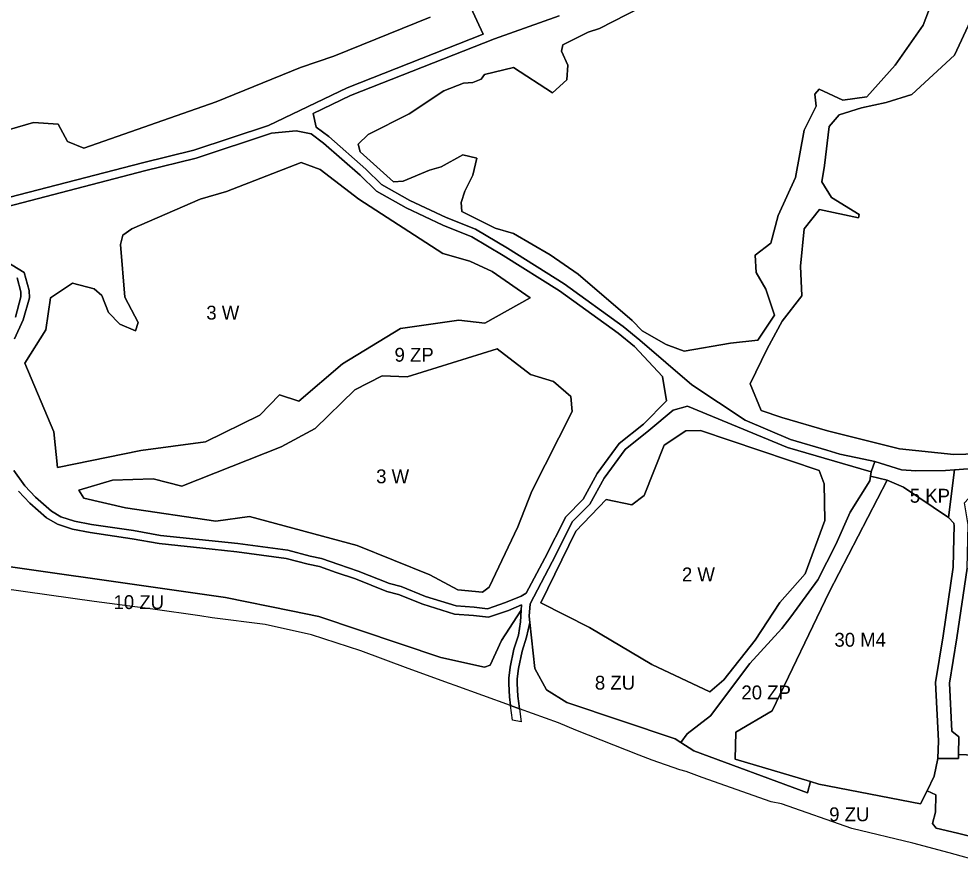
# Model space of a CAD drawing. Extents: x 7437831 to 7440315, y 5545798 to 5547888.
# Drawn here: x 7438706 to 7439385, y 5545907 to 5546523 of the extents above; entities that cross this region are included whole.
import ezdxf

# ---------------------------------------------------------------- set-up
doc = ezdxf.new("R2010")
doc.units = 0
doc.layers.add('linie_rozgraniczajace', color=7, linetype='Continuous')
doc.layers.add('oznaczenia_przeznaczen', color=7, linetype='Continuous')

msp = doc.modelspace()

# ---------------------------------------------------------------- linework, layer by layer
at = {"layer": 'linie_rozgraniczajace'}
for points in [[(7438699.06, 5546673.83), (7438708.8, 5546695.84), (7438713.9, 5546712.14), (7438733.41, 5546751.01), (7438750.34, 5546785.38), (7438759.15, 5546802.74), (7438764.03, 5546813.26), (7438765.56, 5546815.87), (7438771.94, 5546819.42), (7438985.17, 5546680.77), (7439014.11, 5546648.75), (7439017.47, 5546636.36), (7439017.35, 5546621.89), (7439016.94, 5546607.19), (7439014.18, 5546578.97), (7439018.45, 5546567.43), (7439030.64, 5546534.44), (7439041.15, 5546511.43), (7438943, 5546472.84), (7438886.32, 5546445.62), (7438832.51, 5546427.97), (7438795.44, 5546418.73), (7438685.57, 5546390.27)], [(7438685.57, 5546390.27), (7438795.44, 5546418.73), (7438832.51, 5546427.97), (7438886.32, 5546445.62), (7438943, 5546472.84), (7439041.15, 5546511.43), (7439030.64, 5546534.44), (7439018.45, 5546567.43), (7439014.18, 5546578.97), (7439016.94, 5546607.19), (7439017.35, 5546621.89), (7439017.47, 5546636.36), (7439014.11, 5546648.75), (7438985.17, 5546680.77), (7438771.94, 5546819.42), (7438765.56, 5546815.87), (7438764.03, 5546813.26), (7438759.15, 5546802.74), (7438750.34, 5546785.38), (7438733.41, 5546751.01), (7438713.9, 5546712.14), (7438708.8, 5546695.84), (7438699.06, 5546673.83)], [(7439401.45, 5546576.44), (7439379.25, 5546577.57), (7439374.12, 5546559.74), (7439358.43, 5546518.01), (7439338.09, 5546489.26), (7439317.74, 5546466.42), (7439300.33, 5546464.03), (7439283.42, 5546471.79), (7439280.22, 5546468.33), (7439281.31, 5546459.59), (7439272.68, 5546442.36), (7439266.36, 5546408.09), (7439253.82, 5546380.88), (7439248.46, 5546360.85)], [(7439164.87, 5546535.91), (7439125.09, 5546515.56), (7439116.92, 5546513.02), (7439098.56, 5546503.88), (7439097.54, 5546499.33), (7439102.06, 5546489.25), (7439101.55, 5546478.52), (7439091.04, 5546469.2), (7439063.01, 5546487.51), (7439042.01, 5546482.37), (7439039.75, 5546479.03), (7439033.58, 5546476.61), (7439026.99, 5546476.08), (7439012.79, 5546470.71), (7438987.75, 5546454.06), (7438958.16, 5546439.08), (7438950.98, 5546432.24), (7438952.33, 5546426.57), (7438976.57, 5546405.02), (7438983.43, 5546405.41), (7439002.39, 5546413.45), (7439010.83, 5546415.84), (7439026.4, 5546424.54), (7439036.63, 5546422.09), (7439033.54, 5546409.92), (7439027.88, 5546398.25), (7439025.26, 5546390.04), (7439025.83, 5546383.57), (7439049.69, 5546371.71), (7439063.06, 5546367.71), (7439089.41, 5546352.3), (7439109.68, 5546338.47), (7439148.63, 5546305.03), (7439155.7, 5546297.64), (7439173.07, 5546287.72), (7439174.97, 5546286.99), (7439185.95, 5546282.96), (7439219.38, 5546288.65), (7439239.17, 5546290.83), (7439251.23, 5546308.83), (7439244.94, 5546327.59), (7439237.88, 5546339.63), (7439237.29, 5546352.21), (7439248.46, 5546360.85), (7439253.82, 5546380.88), (7439266.36, 5546408.09), (7439272.68, 5546442.36), (7439281.31, 5546459.59), (7439280.22, 5546468.33), (7439283.42, 5546471.79), (7439300.33, 5546464.03), (7439317.74, 5546466.42), (7439338.09, 5546489.26), (7439358.43, 5546518.01), (7439374.12, 5546559.74)], [(7439248.46, 5546360.85), (7439237.29, 5546352.21), (7439237.88, 5546339.63), (7439244.94, 5546327.59), (7439251.23, 5546308.83), (7439239.17, 5546290.83), (7439219.38, 5546288.65), (7439185.95, 5546282.96), (7439174.97, 5546286.99), (7439173.07, 5546287.72), (7439155.7, 5546297.64), (7439148.63, 5546305.03), (7439109.68, 5546338.47), (7439089.41, 5546352.3), (7439063.06, 5546367.71), (7439049.69, 5546371.71), (7439025.83, 5546383.57), (7439025.26, 5546390.04), (7439027.88, 5546398.25), (7439033.54, 5546409.92), (7439036.63, 5546422.09), (7439026.4, 5546424.54), (7439010.83, 5546415.84), (7439002.39, 5546413.45), (7438983.43, 5546405.41), (7438976.57, 5546405.02), (7438952.33, 5546426.57), (7438950.98, 5546432.24), (7438958.16, 5546439.08), (7438987.75, 5546454.06), (7439012.79, 5546470.71), (7439026.99, 5546476.08), (7439033.58, 5546476.61), (7439039.75, 5546479.03), (7439042.01, 5546482.37), (7439063.01, 5546487.51), (7439091.04, 5546469.2), (7439101.55, 5546478.52), (7439102.06, 5546489.25), (7439097.54, 5546499.33), (7439098.56, 5546503.88), (7439116.92, 5546513.02), (7439125.09, 5546515.56), (7439164.87, 5546535.91)], [(7438699.67, 5546442.72), (7438716.97, 5546447.82), (7438734.58, 5546446.64), (7438741.43, 5546434.19), (7438753.16, 5546429.4), (7438848.5, 5546462.71), (7438909.43, 5546487.42), (7438933.42, 5546495.59), (7439002.86, 5546523.66)], [(7439002.86, 5546523.66), (7438933.42, 5546495.59), (7438909.43, 5546487.42), (7438848.5, 5546462.71), (7438753.16, 5546429.4), (7438741.43, 5546434.19), (7438734.58, 5546446.64), (7438716.97, 5546447.82), (7438699.67, 5546442.72)], [(7439095.95, 5546524.77), (7439049.23, 5546508.17), (7438945.4, 5546467.33), (7438918.44, 5546454.39), (7438920.74, 5546444.4), (7438929.86, 5546437.61), (7438956.57, 5546414.17), (7438967.72, 5546403.03), (7438988.32, 5546391.65), (7439014.38, 5546379.2), (7439035.51, 5546370.91), (7439058.75, 5546357.15), (7439099.4, 5546331.47), (7439142.06, 5546300.79), (7439154.08, 5546290.95), (7439191.67, 5546258.77), (7439230.13, 5546233.17), (7439262.63, 5546219.23), (7439288.89, 5546211.59), (7439298.31, 5546208.73), (7439315.6, 5546205.08), (7439323.52, 5546203.36), (7439320.99, 5546196.02), (7439260.6, 5546213.58), (7439188.38, 5546243.2), (7439178.2, 5546240.33), (7439160.56, 5546225.69), (7439143.61, 5546212.17), (7439128.44, 5546191.44), (7439117.98, 5546172.55), (7439105.53, 5546160.06), (7439090.84, 5546130.96), (7439074.92, 5546100.81), (7439074.32, 5546091.83), (7439074.82, 5546087.34), (7439072.38, 5546076.79), (7439069.13, 5546066.7), (7439066.53, 5546054.14), (7439065.7, 5546046.83), (7439065.65, 5546043.25), (7439066.09, 5546034.32), (7439066.92, 5546029.01), (7439067.36, 5546025.17), (7439060.74, 5546027.56), (7439060.11, 5546033.71), (7439059.65, 5546043.15), (7439059.71, 5546047.21), (7439060.6, 5546055.09), (7439063.32, 5546068.23), (7439066.53, 5546078.18), (7439068.05, 5546087.92), (7439068.61, 5546096.26), (7439068.85, 5546100), (7439059.4, 5546096.08), (7439044.88, 5546091.15), (7439034.11, 5546092.42), (7439020.47, 5546093.46), (7438997.61, 5546100.51), (7438979.99, 5546107.49), (7438971.76, 5546109.7), (7438949.01, 5546118.76), (7438935.17, 5546123.37), (7438922.98, 5546127.76), (7438914.96, 5546129.33), (7438899.12, 5546133.51), (7438863.46, 5546138.4), (7438845.67, 5546140.31), (7438807.57, 5546144.23), (7438788, 5546147.71), (7438757.75, 5546152.15), (7438744.93, 5546154.58), (7438734.21, 5546158.12), (7438726.22, 5546162.82), (7438714.2, 5546173.33), (7438706.01, 5546182.06)], [(7439400.62, 5546198.75), (7439380.94, 5546197.47), (7439374.36, 5546197.04), (7439353.15, 5546196.65), (7439342.8, 5546197.49), (7439323.52, 5546203.36), (7439315.6, 5546205.08), (7439298.31, 5546208.73), (7439288.89, 5546211.59), (7439262.63, 5546219.23), (7439230.13, 5546233.17), (7439191.67, 5546258.77), (7439154.08, 5546290.95), (7439142.06, 5546300.79), (7439099.4, 5546331.47), (7439058.75, 5546357.15), (7439035.51, 5546370.91), (7439014.38, 5546379.2), (7438988.32, 5546391.65), (7438967.72, 5546403.03), (7438956.57, 5546414.17), (7438929.86, 5546437.61), (7438920.74, 5546444.4), (7438918.44, 5546454.39), (7438945.4, 5546467.33), (7439049.23, 5546508.17), (7439095.95, 5546524.77)], [(7439423.56, 5546209.6), (7439380.47, 5546208.46), (7439341.2, 5546212.43), (7439289.29, 5546225.51), (7439256.48, 5546235.14), (7439241.51, 5546240.13), (7439233.66, 5546259.37), (7439245.78, 5546284.53), (7439256.59, 5546304.63), (7439270.79, 5546322.75), (7439269.92, 5546344.23), (7439272.48, 5546371.23), (7439283.6, 5546384.98), (7439311.64, 5546379.12), (7439312.27, 5546381.43), (7439292.35, 5546393.79), (7439285.23, 5546404.92), (7439287.18, 5546416.79), (7439290.51, 5546444.98), (7439297.72, 5546453.43), (7439313.99, 5546458.47), (7439331.7, 5546462.18), (7439350.24, 5546467.97), (7439380.9, 5546496.43), (7439392.56, 5546521.09)], [(7439392.56, 5546521.09), (7439380.9, 5546496.43), (7439350.24, 5546467.97), (7439331.7, 5546462.18), (7439313.99, 5546458.47), (7439297.72, 5546453.43), (7439290.51, 5546444.98)], [(7438687, 5546384.45), (7438796.92, 5546412.91), (7438834.17, 5546422.2), (7438888.57, 5546440.05), (7438906.24, 5546441.88), (7438917.16, 5546439.59), (7438926.08, 5546432.94), (7438952.47, 5546409.79), (7438964.08, 5546398.19), (7438985.58, 5546386.31), (7439011.99, 5546373.7), (7439032.87, 5546365.5), (7439055.62, 5546352.03), (7439096.04, 5546326.5), (7439138.41, 5546296.03), (7439150.19, 5546286.39), (7439170.34, 5546264.59), (7439173.21, 5546247.17), (7439156.78, 5546230.34), (7439139.25, 5546216.36), (7439123.38, 5546194.68), (7439113.14, 5546176.19), (7439100.61, 5546163.61), (7439085.51, 5546133.71), (7439072.14, 5546108.39), (7439068.56, 5546106.37), (7439057.28, 5546101.7), (7439044.23, 5546097.27), (7439034.68, 5546098.4), (7439021.59, 5546099.39), (7438999.6, 5546106.18), (7438981.88, 5546113.2), (7438973.66, 5546115.41), (7438951.07, 5546124.39), (7438937.13, 5546129.04), (7438924.58, 5546133.56), (7438916.3, 5546135.18), (7438900.29, 5546139.4), (7438864.19, 5546144.36), (7438808.41, 5546150.18), (7438788.96, 5546153.63), (7438758.74, 5546158.07), (7438746.44, 5546160.4), (7438736.7, 5546163.61), (7438729.75, 5546167.71), (7438718.37, 5546177.65), (7438710.65, 5546185.88), (7438702.73, 5546196.88)], [(7438702.73, 5546196.88), (7438710.65, 5546185.88), (7438718.37, 5546177.65), (7438729.75, 5546167.71), (7438736.7, 5546163.61), (7438746.44, 5546160.4), (7438758.74, 5546158.07), (7438788.96, 5546153.63), (7438808.41, 5546150.18), (7438864.19, 5546144.36), (7438900.29, 5546139.4), (7438916.3, 5546135.18), (7438924.58, 5546133.56), (7438937.13, 5546129.04), (7438951.07, 5546124.39), (7438973.66, 5546115.41), (7438981.88, 5546113.2), (7438999.6, 5546106.18), (7439021.59, 5546099.39), (7439034.68, 5546098.4), (7439044.23, 5546097.27), (7439057.28, 5546101.7), (7439068.56, 5546106.37), (7439072.14, 5546108.39), (7439085.51, 5546133.71), (7439100.61, 5546163.61), (7439113.14, 5546176.19), (7439123.38, 5546194.68), (7439139.25, 5546216.36), (7439156.78, 5546230.34), (7439173.21, 5546247.17), (7439170.34, 5546264.59), (7439150.19, 5546286.39), (7439138.41, 5546296.03), (7439096.04, 5546326.5), (7439055.62, 5546352.03), (7439032.87, 5546365.5), (7439011.99, 5546373.7), (7438985.58, 5546386.31), (7438964.08, 5546398.19), (7438952.47, 5546409.79), (7438926.08, 5546432.94), (7438917.16, 5546439.59), (7438906.24, 5546441.88), (7438888.57, 5546440.05), (7438834.17, 5546422.2), (7438796.92, 5546412.91), (7438687, 5546384.45)], [(7439290.51, 5546444.98), (7439287.18, 5546416.79), (7439285.23, 5546404.92), (7439292.35, 5546393.79), (7439312.27, 5546381.43), (7439311.64, 5546379.12), (7439283.6, 5546384.98), (7439272.48, 5546371.23), (7439269.92, 5546344.23), (7439270.79, 5546322.75), (7439256.59, 5546304.63), (7439245.78, 5546284.53), (7439233.66, 5546259.37), (7439241.51, 5546240.13), (7439256.48, 5546235.14), (7439289.29, 5546225.51), (7439341.2, 5546212.43), (7439380.47, 5546208.46), (7439423.56, 5546209.6)], [(7438703.19, 5546291.86), (7438709.44, 5546305.5), (7438713.88, 5546321.32), (7438713.77, 5546326.6), (7438710.19, 5546339.75), (7438692.64, 5546350.33)], [(7438692.64, 5546350.33), (7438710.19, 5546339.75), (7438713.77, 5546326.6), (7438713.88, 5546321.32), (7438709.44, 5546305.5), (7438703.19, 5546291.86)], [(7438705.04, 5546335.85), (7438707.78, 5546325.74), (7438707.86, 5546322.08), (7438703.79, 5546307.58)], [(7438703.79, 5546307.58), (7438707.86, 5546322.08), (7438707.78, 5546325.74), (7438705.04, 5546335.85)], [(7439389.99, 5546126.42), (7439382.67, 5546076.21), (7439377.24, 5546043.59), (7439379.16, 5546008.91), (7439384.02, 5546004.85), (7439383.92, 5545992.14), (7439383.9, 5545989.36), (7439369.04, 5545989.31), (7439369.31, 5546001.99), (7439367.2, 5546044.17), (7439372.79, 5546077.75), (7439380.01, 5546127.27), (7439380.55, 5546148.21), (7439380.78, 5546157.06), (7439380.49, 5546158.88), (7439376.7, 5546163.04), (7439380.94, 5546197.47), (7439400.62, 5546198.75)], [(7438706.01, 5546182.06), (7438714.2, 5546173.33), (7438726.22, 5546162.82), (7438734.21, 5546158.12), (7438744.93, 5546154.58), (7438757.75, 5546152.15), (7438788, 5546147.71), (7438807.57, 5546144.23), (7438845.67, 5546140.31), (7438863.46, 5546138.4), (7438899.12, 5546133.51), (7438914.96, 5546129.33), (7438922.98, 5546127.76), (7438935.17, 5546123.37), (7438949.01, 5546118.76), (7438971.76, 5546109.7), (7438979.99, 5546107.49), (7438997.61, 5546100.51), (7439020.47, 5546093.46), (7439034.11, 5546092.42), (7439044.88, 5546091.15), (7439059.4, 5546096.08), (7439068.85, 5546100), (7439068.61, 5546096.26), (7439054.32, 5546074.41), (7439046.11, 5546056.67), (7439042.09, 5546055.06), (7439010.65, 5546062.01), (7438922.67, 5546091.62), (7438902.67, 5546095.84), (7438855.21, 5546105.38), (7438641.23, 5546135.98)], [(7438641.23, 5546135.98), (7438855.21, 5546105.38), (7438902.67, 5546095.84), (7438922.67, 5546091.62), (7439010.65, 5546062.01), (7439042.09, 5546055.06), (7439046.11, 5546056.67), (7439054.32, 5546074.41), (7439068.61, 5546096.26), (7439068.05, 5546087.92), (7439066.53, 5546078.18), (7439063.32, 5546068.23), (7439060.6, 5546055.09), (7439059.71, 5546047.21), (7439059.65, 5546043.15), (7439060.11, 5546033.71), (7439060.74, 5546027.56), (7439020.85, 5546041.97), (7439016.86, 5546043.42), (7438987.05, 5546054.19), (7438952.89, 5546066.82), (7438917.26, 5546078.42), (7438883.95, 5546085.91), (7438845.69, 5546090.69), (7438836.78, 5546092.12), (7438803.01, 5546097.03), (7438760.54, 5546102.46), (7438693.97, 5546111.88)], [(7439401.35, 5545914.55), (7439377.07, 5545921.34), (7439350.86, 5545928.25), (7439306.97, 5545938.71), (7439256.27, 5545956.7), (7439248.87, 5545958.09), (7439199.01, 5545975.54), (7439187.44, 5545979.82), (7439182.82, 5545981.12), (7439162.87, 5545988.13), (7439153.49, 5545991.61), (7439107.99, 5546009.8), (7439095.39, 5546015.05), (7439067.36, 5546025.17), (7439066.92, 5546029.01), (7439066.09, 5546034.32), (7439065.65, 5546043.25), (7439065.7, 5546046.83), (7439066.53, 5546054.14), (7439069.13, 5546066.7), (7439072.38, 5546076.79), (7439074.82, 5546087.34), (7439078.44, 5546054.28), (7439086.74, 5546038.75), (7439101.49, 5546029.72), (7439179.66, 5546003.41), (7439183.66, 5546000.85), (7439192.93, 5545994.92), (7439275.05, 5545964.63), (7439277.14, 5545972.67), (7439283.09, 5545970.89), (7439356.55, 5545956.51), (7439361.22, 5545966.06), (7439367.55, 5545963.07), (7439367.18, 5545950.71), (7439365.08, 5545942.43), (7439367.76, 5545939.03), (7439383.16, 5545935.37), (7439495.91, 5545907.34)], [(7439495.91, 5545907.34), (7439383.16, 5545935.37), (7439367.76, 5545939.03), (7439365.08, 5545942.43), (7439367.18, 5545950.71), (7439367.55, 5545963.07), (7439361.22, 5545966.06), (7439366.36, 5545976.59), (7439369.04, 5545989.31), (7439383.9, 5545989.36), (7439383.92, 5545992.14), (7439406.69, 5545991.33)]]:
    msp.add_lwpolyline(points, dxfattribs=at)
for points in [[(7438840.99, 5546217.59), (7438880.15, 5546236.92), (7438894.18, 5546251.37), (7438908.31, 5546246.92), (7438939.58, 5546273.72), (7438981.4, 5546299.33), (7439023.6, 5546305.28), (7439042.27, 5546303.24), (7439074.95, 5546321.49), (7439047.53, 5546340.35), (7439031.52, 5546347.85), (7439011.94, 5546353.36), (7438951.56, 5546392.46), (7438923.48, 5546414.02), (7438909.93, 5546419.07), (7438856.12, 5546398.13), (7438837.11, 5546392.43), (7438787.89, 5546371.15), (7438781.39, 5546366.47), (7438779.67, 5546359.91), (7438782.8, 5546321.8), (7438792.37, 5546303.71), (7438790.48, 5546297.69), (7438779.03, 5546302.39), (7438771.01, 5546310.82), (7438766.11, 5546323.05), (7438760.65, 5546327.95), (7438744.96, 5546331.91), (7438729.15, 5546321.38), (7438725.86, 5546298.31), (7438710.59, 5546274.4), (7438731.66, 5546224.8), (7438734.12, 5546199.14), (7438794.31, 5546211.46)], [(7438840.99, 5546217.59), (7438794.31, 5546211.46), (7438734.12, 5546199.14), (7438731.66, 5546224.8), (7438710.59, 5546274.4), (7438725.86, 5546298.31), (7438729.15, 5546321.38), (7438744.96, 5546331.91), (7438760.65, 5546327.95), (7438766.11, 5546323.05), (7438771.01, 5546310.82), (7438779.03, 5546302.39), (7438790.48, 5546297.69), (7438792.37, 5546303.71), (7438782.8, 5546321.8), (7438779.67, 5546359.91), (7438781.39, 5546366.47), (7438787.89, 5546371.15), (7438837.11, 5546392.43), (7438856.12, 5546398.13), (7438909.93, 5546419.07), (7438923.48, 5546414.02), (7438951.56, 5546392.46), (7439011.94, 5546353.36), (7439031.52, 5546347.85), (7439047.53, 5546340.35), (7439074.95, 5546321.49), (7439042.27, 5546303.24), (7439023.6, 5546305.28), (7438981.4, 5546299.33), (7438939.58, 5546273.72), (7438908.31, 5546246.92), (7438894.18, 5546251.37), (7438880.15, 5546236.92)], [(7439045.51, 5546112.89), (7439066.08, 5546156.32), (7439076.27, 5546182.07), (7439105.21, 5546239.48), (7439104.37, 5546250.16), (7439091.9, 5546261.07), (7439075.16, 5546266.12), (7439051.11, 5546284.69), (7438986.29, 5546264.56), (7438968.28, 5546265.11), (7438948.53, 5546255), (7438919.87, 5546227.12), (7438895.48, 5546213.93), (7438823.82, 5546185.72), (7438803.21, 5546191.02), (7438773.75, 5546190.07), (7438749.55, 5546182.66), (7438753.24, 5546177.08), (7438783.26, 5546170.12), (7438848.36, 5546160.4), (7438872.71, 5546163.86), (7438950.29, 5546142.9), (7439002.73, 5546121.64), (7439022.89, 5546110.99), (7439040.71, 5546109.2)], [(7439045.51, 5546112.89), (7439040.71, 5546109.2), (7439022.89, 5546110.99), (7439002.73, 5546121.64), (7438950.29, 5546142.9), (7438872.71, 5546163.86), (7438848.36, 5546160.4), (7438783.26, 5546170.12), (7438753.24, 5546177.08), (7438749.55, 5546182.66), (7438773.75, 5546190.07), (7438803.21, 5546191.02), (7438823.82, 5546185.72), (7438895.48, 5546213.93), (7438919.87, 5546227.12), (7438948.53, 5546255), (7438968.28, 5546265.11), (7438986.29, 5546264.56), (7439051.11, 5546284.69), (7439075.16, 5546266.12), (7439091.9, 5546261.07), (7439104.37, 5546250.16), (7439105.21, 5546239.48), (7439076.27, 5546182.07), (7439066.08, 5546156.32)], [(7439188.38, 5546243.2), (7439260.6, 5546213.58), (7439320.99, 5546196.02), (7439320.51, 5546192.9), (7439319.98, 5546189.4), (7439305.67, 5546166.84), (7439295.37, 5546143.59), (7439282.36, 5546118.13), (7439263.03, 5546091.51), (7439256.36, 5546083.09), (7439233.48, 5546057.75), (7439204.95, 5546020.01), (7439188.18, 5546007.15), (7439183.66, 5546000.85), (7439179.66, 5546003.41), (7439101.49, 5546029.72), (7439086.74, 5546038.75), (7439078.44, 5546054.28), (7439074.82, 5546087.34), (7439074.32, 5546091.83), (7439074.92, 5546100.81), (7439090.84, 5546130.96), (7439105.53, 5546160.06), (7439117.98, 5546172.55), (7439128.44, 5546191.44), (7439143.61, 5546212.17), (7439160.56, 5546225.69), (7439178.2, 5546240.33)], [(7439171.56, 5546215.2), (7439157.3, 5546178.83), (7439148.3, 5546172.1), (7439129.75, 5546176.06), (7439108.04, 5546153.16), (7439082.77, 5546101.56), (7439117.88, 5546083.8), (7439162.82, 5546057.15), (7439204.63, 5546037.38), (7439214.55, 5546045.91), (7439237.21, 5546074.49), (7439255.12, 5546101.73), (7439273.31, 5546122.44), (7439287.56, 5546160.9), (7439287.03, 5546187.23), (7439283.33, 5546196.98), (7439197.74, 5546225.81), (7439187.13, 5546225.41)], [(7439171.56, 5546215.2), (7439187.13, 5546225.41), (7439197.74, 5546225.81), (7439283.33, 5546196.98), (7439287.03, 5546187.23), (7439287.56, 5546160.9), (7439273.31, 5546122.44), (7439255.12, 5546101.73), (7439237.21, 5546074.49), (7439214.55, 5546045.91), (7439204.63, 5546037.38), (7439162.82, 5546057.15), (7439117.88, 5546083.8), (7439082.77, 5546101.56), (7439108.04, 5546153.16), (7439129.75, 5546176.06), (7439148.3, 5546172.1), (7439157.3, 5546178.83)], [(7439323.52, 5546203.36), (7439342.8, 5546197.49), (7439353.15, 5546196.65), (7439374.36, 5546197.04), (7439380.94, 5546197.47), (7439376.7, 5546163.04), (7439344.15, 5546184.96), (7439332.3, 5546189.96), (7439320.51, 5546192.9), (7439320.99, 5546196.02)], [(7439320.51, 5546192.9), (7439332.3, 5546189.96), (7439290.5, 5546109.1), (7439249.55, 5546023.67), (7439223.41, 5546008.16), (7439222.78, 5545988.89), (7439277.14, 5545972.67), (7439275.05, 5545964.63), (7439192.93, 5545994.92), (7439183.66, 5546000.85), (7439188.18, 5546007.15), (7439204.95, 5546020.01), (7439233.48, 5546057.75), (7439256.36, 5546083.09), (7439263.03, 5546091.51), (7439282.36, 5546118.13), (7439295.37, 5546143.59), (7439305.67, 5546166.84), (7439319.98, 5546189.4)], [(7439332.3, 5546189.96), (7439344.15, 5546184.96), (7439376.7, 5546163.04), (7439380.49, 5546158.88), (7439380.78, 5546157.06), (7439380.55, 5546148.21), (7439380.01, 5546127.27), (7439372.79, 5546077.75), (7439367.2, 5546044.17), (7439369.31, 5546001.99), (7439369.04, 5545989.31), (7439366.36, 5545976.59), (7439361.22, 5545966.06), (7439356.55, 5545956.51), (7439283.09, 5545970.89), (7439277.14, 5545972.67), (7439222.78, 5545988.89), (7439223.41, 5546008.16), (7439249.55, 5546023.67), (7439290.5, 5546109.1)], [(7439433.75, 5546194.86), (7439454.14, 5546102.8), (7439451.23, 5545991.15), (7439406.69, 5545991.33), (7439383.92, 5545992.14), (7439384.02, 5546004.85), (7439379.16, 5546008.91), (7439377.24, 5546043.59), (7439382.67, 5546076.21), (7439389.99, 5546126.42), (7439390.8, 5546157.73), (7439388.24, 5546173.71), (7439402.13, 5546188.86), (7439422.48, 5546192.72)], [(7439060.74, 5546027.56), (7439067.36, 5546025.17), (7439068.44, 5546015.66), (7439062.25, 5546016.99)]]:
    msp.add_lwpolyline(points, close=True, dxfattribs=at)

# ---------------------------------------------------------------- texts
at = {"layer": 'oznaczenia_przeznaczen'}
for s, p in [('3 W', (7438841.4943, 5546305.73)), ('9 ZP', (7438977.2029, 5546275.35)), ('3 W', (7438963.9543, 5546187.71)), ('5 KP', (7439348.7253, 5546173.71)), ('2 W', (7439184.4343, 5546116.99)), ('10 ZU', (7438774.5808, 5546097.03)), ('30 M4', (7439294.3905, 5546069.9)), ('8 ZU', (7439121.6653, 5546038.93)), ('20 ZP', (7439227.3183, 5546031.92)), ('9 ZU', (7439290.6053, 5545944.06))]:
    msp.add_text(s, height=10, dxfattribs=at).set_placement(p)

doc.saveas('drawing.dxf')
